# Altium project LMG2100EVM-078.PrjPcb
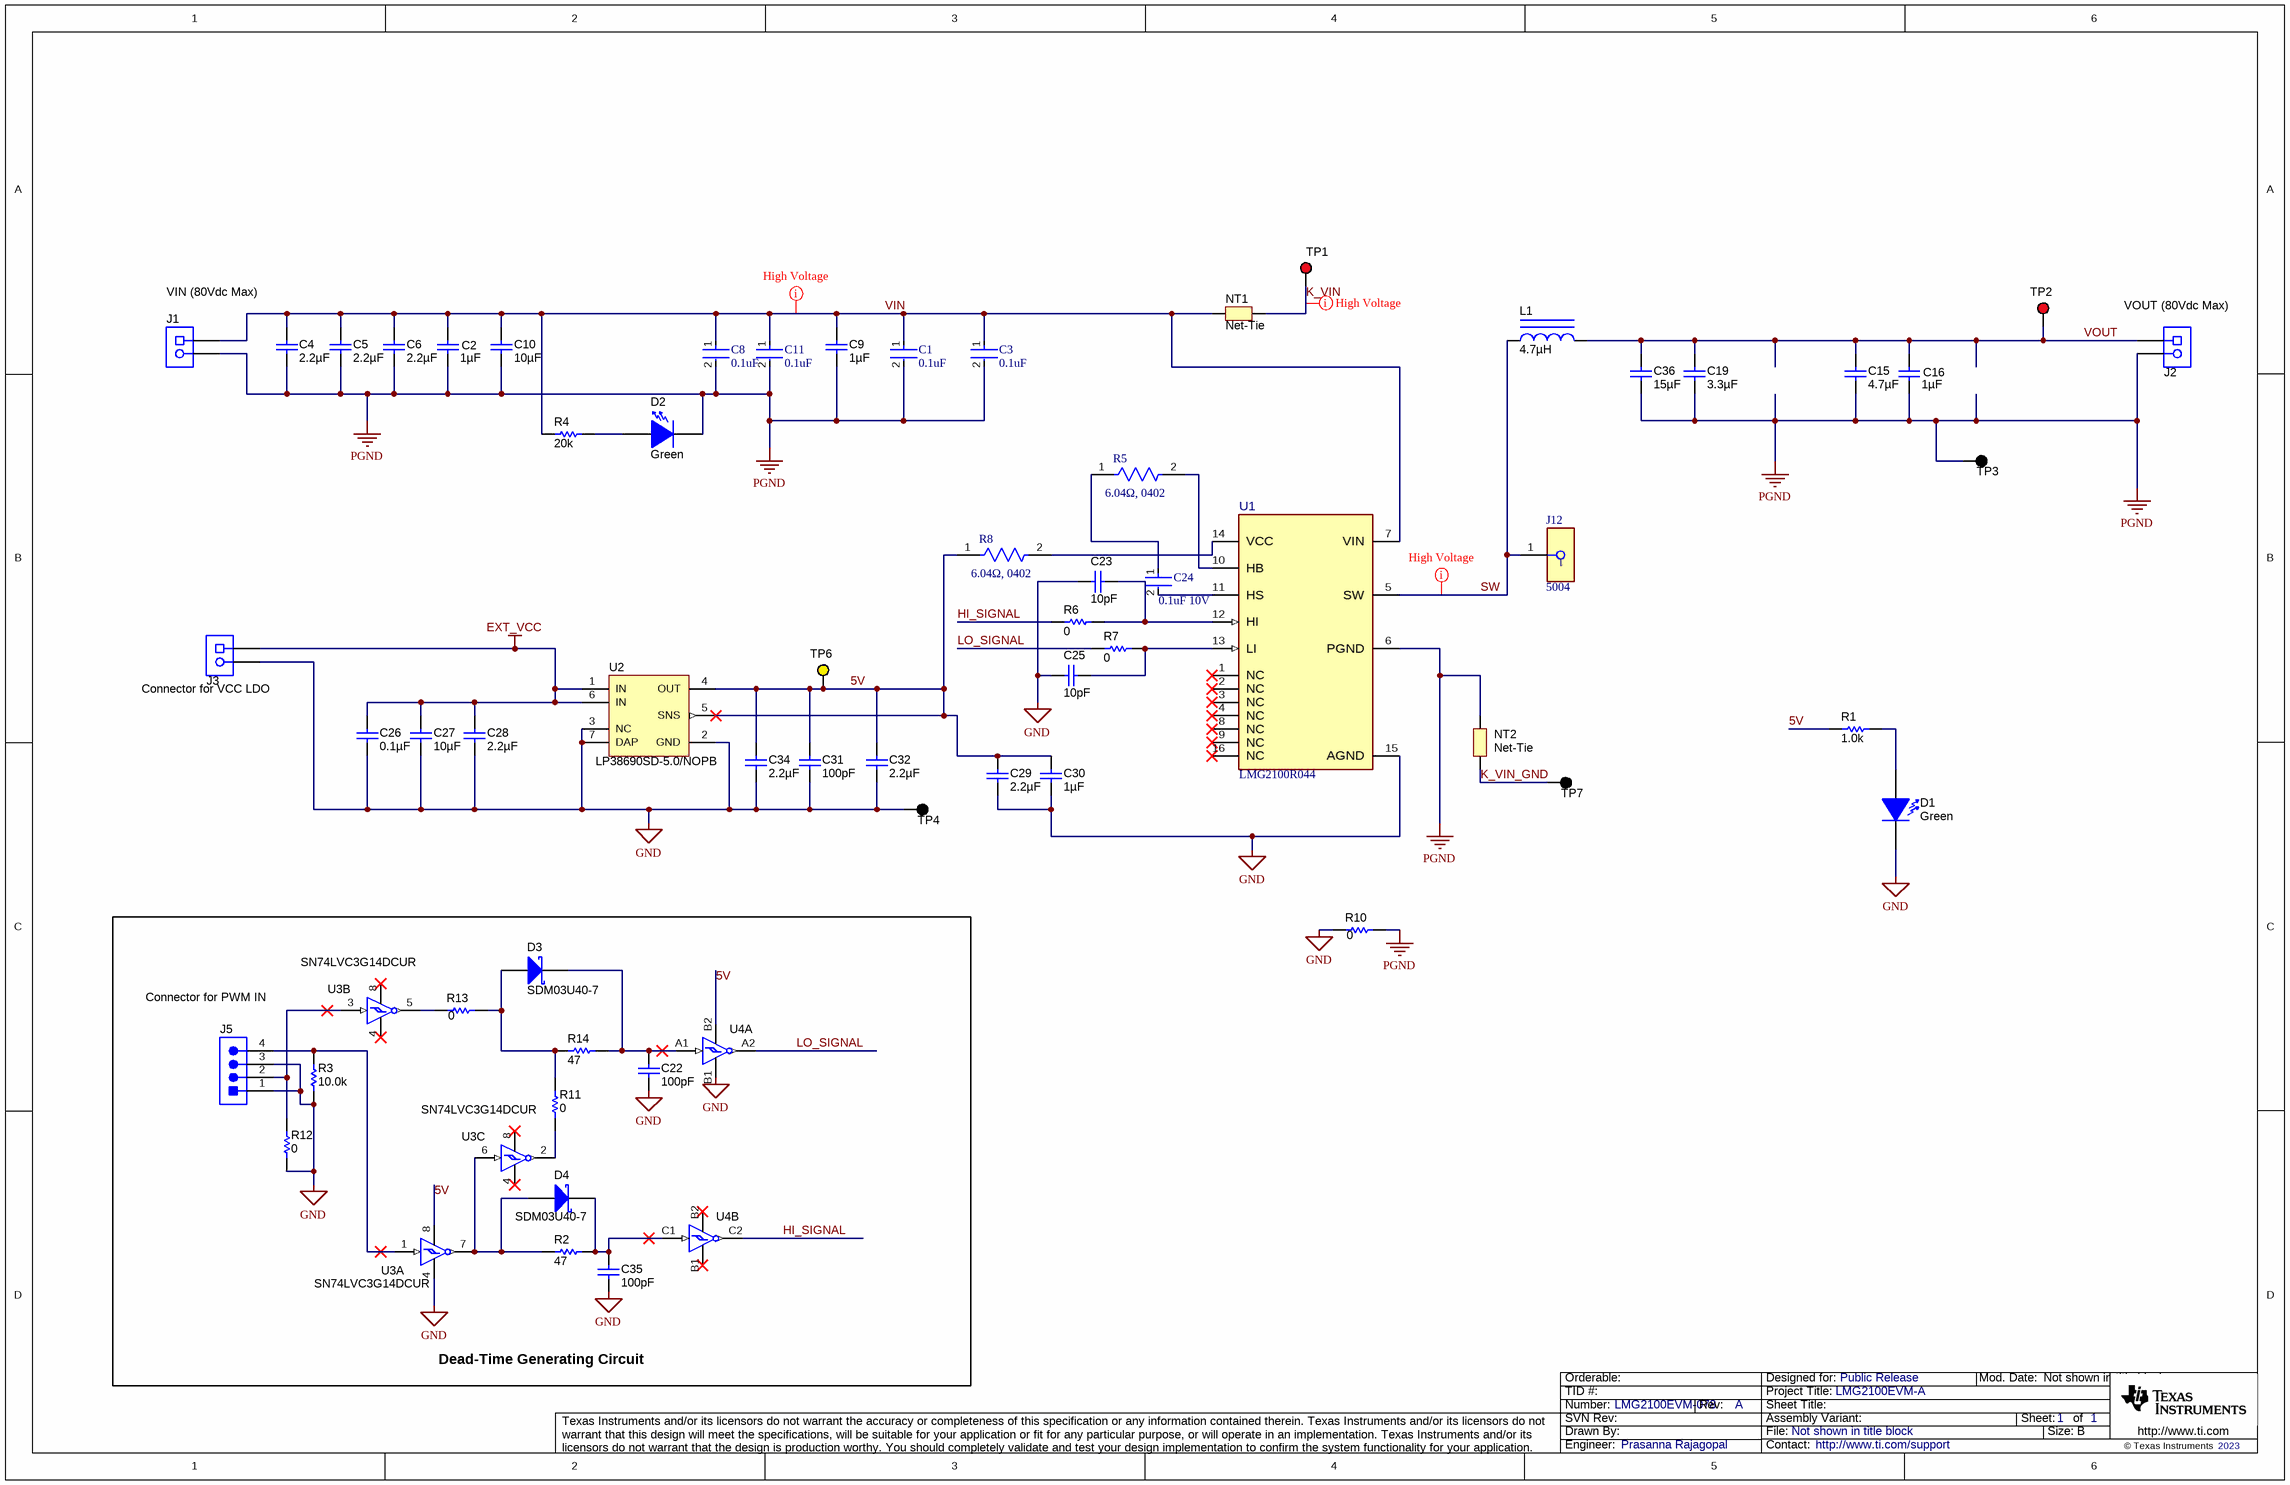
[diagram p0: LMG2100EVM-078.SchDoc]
CopyrightYear: 2023; PCB_Layout: Prasanna Rajagopal; PCB_Rev: A; PRJ_Customer: Public Release; PRJ_Engineer: Prasanna Rajagopal; PRJ_Number: LMG2100EVM-078; PRJ_Title: LMG2100EVM-A; SCH_Rev: A; TechSupport: http://www.ti.com/support
2 sheets, 79 parts. Net scope: global (net labels, ports and power ports of the same name join across sheets).
Board file: LMG2100EVM-078.PcbDoc
Sheets:
  LMG2100EVM-078.SchDoc
  LMG2100EVM-078_hardware.SchDoc

## Sheet LMG2100EVM-078.SchDoc
size 431 x 279 mm; Date: Not shown in title block; ApprovedBy: Not shown in title block; CheckedBy: Not shown in title block; Author: Not shown in title block; CompanyName: Not shown in title block; Engineer: Not shown in title block; Organization: Not shown in title block; Address1: Not shown in title block; Address2: Not shown in title block; Address3: Not shown in title block; Address4: Not shown in title block; DocumentNumber: 1; Revision: Use project parameter SCH_Rev; SheetNumber: 1; SheetTotal: 1; PageSetup: Record=PageOptions¦CenterHorizontal=True¦CenterVertical=True¦PrintScale=1.00¦XCorrection=1.00¦YCorrection=1.00¦PrintKind=0¦BorderSize=5000000¦LeftOffset=0¦BottomOffset=0¦Orientation=2¦PaperLength=1000¦PaperWidth=1000¦Scale=100¦PaperSource=15¦PrintQuality=600¦MediaType=1¦DitherType=10¦PaperKind=Letter¦PrintScaleMode=1

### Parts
C1  0.1uF  [FP-GRM155-0_05-IPC_A]
C2  ValueDisplayed: 1µF  [1206]  (hidden comment: C3216X7R2A105M160AA)
C3  0.1uF  [FP-GRM155-0_05-IPC_A]
C4  ValueDisplayed: 2.2µF  [1210_270]  (hidden comment: GRM32ER72A225KA35L)
C5  ValueDisplayed: 2.2µF  [1210_270]  (hidden comment: GRM32ER72A225KA35L)
C6  ValueDisplayed: 2.2µF  [1210_270]  (hidden comment: GRM32ER72A225KA35L)
C8  0.1uF  [FP-GRM155-0_05-IPC_A]
C9  ValueDisplayed: 1µF  [1206]  (hidden comment: C3216X7R2A105M160AA)
C10  ValueDisplayed: 10µF  [2220_280]  (hidden comment: 22201C106MAT2A)
C11  0.1uF  [FP-GRM155-0_05-IPC_A]
C15  ValueDisplayed: 4.7µF  [1210]  (hidden comment: C3225X7S2A475K200AE)
C16  ValueDisplayed: 1µF  [0805_HV]  (hidden comment: C2012X7S2A105K125AB)
C19  ValueDisplayed: 3.3µF  [1206_190]  (hidden comment: C3216X7S2A335M160AB)
C22  ValueDisplayed: 100pF  [0402]  (hidden comment: CC0402JRNPO9BN101)
C23  ValueDisplayed: 10pF  [0402]  (hidden comment: GRM1555C1H100JA01D)
C24  0.1uF 10V  [FP-C1005-050-0_05-IPC_A]
C25  ValueDisplayed: 10pF  [0402]  (hidden comment: GRM1555C1H100JA01D)
C26  ValueDisplayed: 0.1µF  [0603]  (hidden comment: 0603YC104JAT2A)
C27  ValueDisplayed: 10µF  [0805_HV]  (hidden comment: C2012X5R1E106K125AB)
C28  ValueDisplayed: 2.2µF  [0805_HV]  (hidden comment: C0805C225K4RACTU)
C29  ValueDisplayed: 2.2µF  [0805_HV]  (hidden comment: C0805C225K4RACTU)
C30  ValueDisplayed: 1µF  [0402]  (hidden comment: C1005X5R1E105K050BC)
C31  ValueDisplayed: 100pF  [0603]  (hidden comment: 06033C101KAT2A)
C32  ValueDisplayed: 2.2µF  [0603_HV]  (hidden comment: GRM188R71A225KE15D)
C34  ValueDisplayed: 2.2µF  [0603_HV]  (hidden comment: GRM188R71A225KE15D)
C35  ValueDisplayed: 100pF  [0402]  (hidden comment: CC0402JRNPO9BN101)
C36  ValueDisplayed: 15µF  [2220_280]  (hidden comment: C5750X7S2A156M250KB)
D1  value Green  [LTST-C170KGKT_Green]  (hidden comment: VCC_5V)
D2  value Green  [LTST-C170KGKT_Green]  (hidden comment: VIN)
D3  SDM03U40-7  [SOD-523]
D4  SDM03U40-7  [SOD-523]
J1  VIN (80Vdc Max)  [TEC_282841-2]
J2  VOUT (80Vdc Max)  [TEC_282841-2]
J3  282834-2  [TEC_282834-2]  (value not drawn)
J5  5-146278-4  [TE_5-146278-4]  (value not drawn)
J12  5004  [FP-5004-MFG]
L1  ValueDisplayed: 4.7µH  [XAL8080]  (hidden comment: XAL1010-472ME)
NT1  Net-Tie  [Net-Tie_10milWide_30milLong]  (net tie, no BOM)
NT2  Net-Tie  [Net-Tie_10mil]  (net tie, no BOM)
R1  value 1.0k  [0603]  (hidden comment: CRCW06031K00JNEA)
R2  value 47  [0402]  (hidden comment: CRCW040247R0JNED)
R3  value 10.0k  [0402]  (hidden comment: CRCW040210K0FKED)
R4  value 20k  [1206]  (hidden comment: CRCW120620K0JNEA)
R5  6.04Ω, 0402  [FP-CRCW0402-e3-IPC_A]
R6  value 0  [0603]  (hidden comment: CRCW06030000Z0EA)
R7  value 0  [0603]  (hidden comment: CRCW06030000Z0EA)
R8  6.04Ω, 0402  [FP-CRCW0402-e3-IPC_A]
R10  value 0  [0603]  (hidden comment: CRCW06030000Z0EA)
R11  value 0  [0402]  (hidden comment: CRCW04020000Z0ED)
R12  value 0  [0402]  (hidden comment: CRCW04020000Z0ED)
R13  value 0  [0402]  (hidden comment: CRCW04020000Z0ED)
R14  value 47  [0402]  (hidden comment: CRCW040247R0JNED)
TP1  5000  [Keystone5000]  (value not drawn)
TP2  VOUT Sense+  [Keystone5000]  (value not drawn)
TP3  VOUT Sense-  [Keystone5001]  (value not drawn)
TP4  5001  [Keystone5001]  (value not drawn)
TP6  5004  [Keystone5004]  (value not drawn)
TP7  5001  [Keystone5001]  (value not drawn)
U1  LMG2100R044  [RAR0016A-MFG]
U2  LP38690SD-5.0/NOPB  [SDE06A_full]
U3  SN74LVC3G14DCUR  [DCU0008A_N]  (parts A,B,C of 3)
U4  SN74LVC2G14YZPR  [YZP0006ADBD]  (value not drawn)  (parts A,B of 2)

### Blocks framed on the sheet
Dead-Time Generating Circuit: C22 C35 D3 D4 J5 R2 R3 R11-R14 U3 U4

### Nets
EXT_VCC: C26.1 C27.2 C28.2 J3.1 U2.1(IN) U2.6(IN)
GND: C22.2 C23.1 C25.2 C26.2 C27.1 C28.1 C29.1 C30.2 C31.1 C32.2 C34.2 C35.2 D1.2(K) J3.2 J5.1 J5.3 R3.2 R10.2 R12.1 TP4.1 U1.15(AGND) U2.2(GND) U2.3(NC) U2.7(DAP) U3.4(GND) U4.B1(GND)
PGND: C1.2 C2.1 C3.2 C4.2 C5.2 C6.2 C8.2 C9.1 C10.1 C11.2 C15.2 C16.2 C19.2 C36.2 D2.2(K) J1.2 J2.2 NT2.2 R10.1 TP3.1 U1.6(PGND)
5V: C29.2 C30.1 C31.2 C32.1 C34.1 R1.1 R8.1 TP6.1 U2.4(OUT) U2.5(SNS) U3.8(VCC) U4.B2(VCC)
HI_SIGNAL: R6.2 U4.C2(2Y)
K_VIN: NT1.2 TP1.1
K_VIN_GND: NT2.1 TP7.1
LO_SIGNAL: R7.2 U4.A2(1Y)
SW: J12.1 L1.1 U1.5(SW)
VIN: C1.1 C2.2 C3.1 C4.1 C5.1 C6.1 C8.1 C9.2 C10.2 C11.1 J1.1 NT1.1 R4.1 U1.7(VIN)
VOUT: C15.1 C16.1 C19.1 C36.1 J2.1 L1.2 TP2.1
NetC22_1: C22.1 D3.1(K) R14.2 U4.A1(1A)
NetC23_2: C23.2 R6.1 U1.12(HI)
NetC24_1: C24.1 R5.1
NetC24_2: C24.2 U1.11(HS)
NetC25_1: C25.1 R7.1 U1.13(LI)
NetC35_1: C35.1 D4.1(K) R2.2 U4.C1(2A)
NetD1_1: D1.1(A) R1.2
NetD2_1: D2.1(A) R4.2
NetD3_2: D3.2(A) R11.1 R13.2 R14.1
NetD4_2: D4.2(A) R2.1 U3.6(3A) U3.7(1Y)
NetJ5_2: J5.2 R12.2 U3.3(2A)
NetJ5_4: J5.4 R3.1 U3.1(1A)
NetR5_2: R5.2 U1.10(HB)
NetR8_2: R8.2 U1.14(VCC)
NetR11_2: R11.2 U3.2(3Y)
NetR13_1: R13.1 U3.5(2Y)

Not connected (* = marked no-connect by the designer): U1 1(NC)* 2(NC)* 3(NC)* 4(NC)* 8(NC)* 9(NC)* 16(NC)*

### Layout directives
rule Routing Corners [Style - 45 Degree    Min Setback = 100mil    Max Setback = 100mil]; rule Clearance Constraint [Clearance = 25mil]: SW, VIN
rule Routing Corners [Style - 45 Degree    Min Setback = 100mil    Max Setback = 100mil]; rule Clearance Constraint [Clearance = 23.6mil]: K_VIN

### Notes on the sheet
- (near J3) Connector for VCC LDO
- (near J5) Connector for PWM IN

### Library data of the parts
C1 C3 C8 C11 = CMP-06035-008289-1: Chip Multilayer Ceramic Capacitors for General Purpose, 0402, 0.10uF, X5R, 15%, 10%, 100V; Capacitance: 100nF
C2 C9 = C3216X7R2A105M160AA: CAP, CERM, 1uF, 100V, +/-20%, X7R, 1206; Manufacturer: TDK; CompType: Capacitor; VDC_V: 100; Tolerance_%: 20; Polarized: N; TaMax_C: 125; TaMin_C: -55; Cap_F: 0.000001; U/M: EA; Value1: Unknown
C4-C6 = GRM32ER72A225KA35L: CAP, CERM, 2.2 µF, 100 V, +/- 10%, X7R, 1210; Manufacturer: MuRata; Polarized: N; CompType: Capacitor; Value: 2.2uF; U/M: EA; Cap_F: 0.0000022; Tolerance_%: 10; ESR_ohm: 0.007; Value1: 0.007 ohm; VDC_V: 100; Value2: 100V; IRMS_A: 4.4; TaMin_C: -55; TaMax_C: 125; Cap_Case: 1210; SizeArea_mm2: 8; SizeAreaWB_mm2: 14.7; SizeX_mm: 3.2; SizeY_mm: 2.5; SizeZ_mm: 2.7; AEC Category: Q200
C10 = 22201C106MAT2A: CAP, CERM, 10 µF, 100 V, +/- 20%, X7R, 2220; Manufacturer: AVX; CompType: Capacitor; Value: 10uF; VDC_V: 100; Tolerance_%: 20; Cap_Case: 2220; Polarized: N; TaMax_C: 125; TaMin_C: -55; Cap_F: 0.00001; U/M: EA; Value1: Unknown; Value2: 100V; SizeArea_mm2: 28.5; SizeAreaWB_mm2: 53.9; SizeX_mm: 5.7; SizeY_mm: 5; SizeZ_mm: 2.8; AEC Category: Q200
C15 = C3225X7S2A475K200AE: CAP, CERM, 4.7 µF, 100 V, +/- 10%, X7S, 1210; Manufacturer: TDK; CompType: Capacitor; VDC_V: 100; Tolerance_%: 10; Value: 4.7uF; Polarized: N; TaMax_C: 125; TaMin_C: -55; Cap_F: 0.0000047; U/M: EA; Value1: Unknown; Value2: 100V; SizeArea_mm2: 8; SizeAreaWB_mm2: 14.7; SizeX_mm: 3.2; SizeY_mm: 2.5; SizeZ_mm: 1.35; AEC Category: Q200
C16 = C2012X7S2A105K125AB: CAP, CERM, 1 µF, 100 V, +/- 10%, X7S, 0805; Manufacturer: TDK; Cap_Case: 0805; ESR_ohm: 0.008255; IRMS_A: 2.27442; Polarized: N; TaMax_C: 125; TaMin_C: -55; Tolerance_%: 10; VDC_V: 100; Cap_F: 0.000001; CompType: Capacitor; Value: 1uF; U/M: EA; Value1: 0.008255 ohm; Value2: 100V; SizeArea_mm2: 2.5; SizeAreaWB_mm2: 6.75; SizeX_mm: 2; SizeY_mm: 1.25; SizeZ_mm: 1.45; AEC Category: Q200
C19 = C3216X7S2A335M160AB: CAP, CERM, 3.3 µF, 100 V, +/- 20%, X7S, 1206_190; Manufacturer: TDK; Polarized: N; CompType: Capacitor; Value: 3.3uF; U/M: EA; Cap_F: 0.0000033; Tolerance_%: 20; ESR_ohm: 0.003048; Value1: 0.003048 ohm; VDC_V: 100; Value2: 100V; IRMS_A: 4.15703; TaMin_C: -55; TaMax_C: 125; SizeArea_mm2: 5.12; SizeAreaWB_mm2: 10.92; SizeX_mm: 3.2; SizeY_mm: 1.6; SizeZ_mm: 1.9; AEC Category: Q200
C22 C35 = CC0402JRNPO9BN101: CAP, CERM, 100pF, 50V, +/-5%, C0G/NP0, 0402; Manufacturer: Yageo America; Polarized: N; CompType: Capacitor; U/M: EA; Cap_F: 0.0000000001; Tolerance_%: 5; Value1: Unknown; VDC_V: 50; TaMin_C: -55; TaMax_C: 125
C23 C25 = GRM1555C1H100JA01D: CAP, CERM, 10pF, 50V, +/-5%, C0G/NP0, 0402; Manufacturer: MuRata; Polarized: N; CompType: Capacitor; U/M: EA; Cap_F: 0.00000000001; Tolerance_%: 5; Value1: Unknown; VDC_V: 50; TaMin_C: -55; TaMax_C: 125
C24 = CMP-08246-002729-1: Multilayer Ceramic Capacitors 100nF ±10% 10V X5R SMD 0402
C26 = 0603YC104JAT2A: CAP, CERM, 0.1 µF, 16 V, +/- 5%, X7R, 0603; Manufacturer: AVX; ESR_ohm: 0.039; Polarized: N; TaMax_C: 125; TaMin_C: -55; Tolerance_%: 5; VDC_V: 16; Cap_F: 0.0000001; CompType: Capacitor; Value: 0.1uF; U/M: EA; Value1: 0.039 ohm; Value2: 16V
C27 = C2012X5R1E106K125AB: CAP, CERM, 10uF, 25V, +/-10%, X5R, 0805; Manufacturer: TDK; CompType: Capacitor; VDC_V: 25; Tolerance_%: 10; Cap_Case: 0805; Polarized: N; TaMax_C: 85; TaMin_C: -55; Cap_F: 0.00001; U/M: EA; Value1: Unknown
C28 C29 = C0805C225K4RACTU: CAP, CERM, 2.2uF, 16V, +/-10%, X7R, 0805; Manufacturer: Kemet; CompType: Capacitor; VDC_V: 16; Tolerance_%: 10; Cap_Case: 0805; ESR_Ohm: 0.008; IRMS_A: 15.55; Polarized: N; TaMax_C: 125; TaMin_C: -55; Cap_F: 0.0000022; U/M: EA; Value1: 0.008 ohm
C30 = C1005X5R1E105K050BC: CAP, CERM, 1uF, 25V, +/-10%, X5R, 0402; Manufacturer: TDK; Polarized: N; TaMax_C: 80; TaMin_C: -55; Tolerance_%: 10; VDC_V: 25; Cap_F: 0.000001; CompType: Capacitor; U/M: EA; Value1: Unknown
C31 = 06033C101KAT2A: CAP, CERM, 100pF, 25V, +/-10%, X7R, 0603; Manufacturer: AVX; Polarized: N; TaMax_C: 125; TaMin_C: -55; Tolerance_%: 10; VDC_V: 25; Cap_F: 0.0000000001; CompType: Capacitor; U/M: EA
C32 C34 = GRM188R71A225KE15D: CAP, CERM, 2.2uF, 10V, +/-10%, X7R, 0603; Manufacturer: MuRata; Cap_Case: 0603; ESR_Ohm: 0.009; Polarized: N; TaMax_C: 125; TaMin_C: -55; Tolerance_%: 10; Cap_F: 0.0000022; CompType: Capacitor; U/M: EA; Value1: 0.009 ohm
C36 = C5750X7S2A156M250KB: CAP, CERM, 15 µF, 100 V, +/- 20%, X7S, 2220; Manufacturer: TDK; CompType: Capacitor; VDC_V: 100; Tolerance_%: 20; Value: 15uF; ESR_ohm: 0.002642; IRMS_A: 5.61617; Polarized: N; TaMax_C: 125; TaMin_C: -55; Cap_F: 0.000015; U/M: EA; Value1: 0.002642 ohm; Value2: 100V; SizeArea_mm2: 28.5; SizeAreaWB_mm2: 53.9; SizeX_mm: 5.7; SizeY_mm: 5; SizeZ_mm: 2.8; AEC Category: Q200
D1 D2 = LTST-C170KGKT: LED, Green, SMD; Manufacturer: Lite-On; Type: AlInGaP; Vf_V: 2; Value2: 2V; Io_A: 0.02; Value1: W; U/M: EA
D3 D4 = SDM03U40-7: Diode, Schottky, 40V, 0.03A, SOD-523; Manufacturer: Diodes Inc.; U/M: EA; Vf_V: 1; Value2: 1V; Io_A: 0.03; Vr_V: 40; TJmax_C: 125
J1 J2 = 282841-2: Terminal Block, 2x1, 5.08mm, TH; Manufacturer: TE Connectivity; SymbolCreator: a0412235; U/M: EA
J3 = 282834-2: Terminal Block, 2x1, 2.54mm, TH; Manufacturer: TE Connectivity; SymbolCreator: a0412235; U/M: EA
J5 = 5-146278-4: Header, 100mil, 4x1, Tin, TH; Manufacturer: TE Connectivity; SymbolCreator: a0412235; U/M: EA
J12 = CMP-2000-05575-2: PC TEST POINT MINIATURE YELLOW; Manufacturer: Keystone; Number Of Contacts: 1; Is Female: yes
L1 = XAL8080-472ME: Inductor, Shielded, Composite, 4.7 µH, 10.5 A, 0.00889 ohm, SMD; Manufacturer: Coilcraft; Value: 4.7uH; Ind_H: 4.7E-6; Imax_A: 10.5; Irms: 10.5A @ 20C rise; Isat: 17.4A @ 20% inductance drop; Value2: 10.5A; SizeAreaWB_mm2: 107.06; SizeArea_mm2: 69.66; SizeX_mm: 8.1; SizeY_mm: 8.6; SizeZ_mm: 8; AEC Category: Q200
NT1 NT2 = Net-Tie: Single point connection between nets.; SymbolCreator: codlsc
R1 = CRCW06031K00JNEA: RES, 1.0k ohm, 5%, 0.1W, 0603; Manufacturer: Vishay-Dale; CompType: Resistor; Res_ohm: 1000; Value_Code: 1k00; Tolerance_%: 5; Power_W: 0.1; VDC_V: 75; TempCo: 200 ppm/C; EIA_Code: E24; U/M: EA
R2 R14 = CRCW040247R0JNED: RES, 47 ohm, 5%, 0.063W, 0402; Manufacturer: Vishay-Dale; CompType: Resistor; Value_Code: 47R0; Tolerance_%: 5; Power_W: 0.063; VDC_V: 50; TempCo: 200 ppm/C; EIA_Code: E24; U/M: EA
R3 = CRCW040210K0FKED: RES, 10.0k ohm, 1%, 0.063W, 0402; Manufacturer: Vishay-Dale; CompType: Resistor; Res_ohm: 10000; Value_Code: 10k0; Tolerance_%: 1; Power_W: 0.063; VDC_V: 50; TempCo: 100 ppm/C; EIA_Code: E96; U/M: EA
R4 = CRCW120620K0JNEA: RES, 20k ohm, 5%, 0.25W, 1206; Manufacturer: Vishay-Dale; CompType: Resistor; Res_ohm: 20000; Value_Code: 20k0; Tolerance_%: 5; Power_W: 0.25; VDC_V: 200; TempCo: 200 ppm/C; EIA_Code: E24; U/M: EA
R5 R8 = CMP-1011-00259-3: RES Thick Film, 6.04Ω, 1%, 0.063W, 100ppm/°C, 0402; Voltage Rating: 50V; Resistance: 6.04R; Power Rating: 63mW
R6 R7 R10 = CRCW06030000Z0EA: RES, 0 ohm, 5%, 0.1W, 0603; Manufacturer: Vishay-Dale; CompType: Resistor; Value_Code: 0000; Tolerance_%: 5; Power_W: 0.1; VDC_V: 75; TempCo: 200 ppm/C; EIA_Code: E24; U/M: EA
R11-R13 = CRCW04020000Z0ED: RES, 0 ohm, 5%, 0.063W, 0402; Manufacturer: Vishay-Dale; CompType: Resistor; Value_Code: 0000; Tolerance_%: 5; Power_W: 0.063; VDC_V: 50; TempCo: 200 ppm/C; EIA_Code: E24; U/M: EA
TP1 TP2 = 5000: Test Point, Miniature, Red, TH; Manufacturer: Keystone; CompType: Test Point Loop; U/M: EA
TP3 TP4 TP7 = 5001: Test Point, Miniature, Black, TH; Manufacturer: Keystone; CompType: Test Point Loop; U/M: EA
TP6 = 5004: Test Point, Miniature, Yellow, TH; Manufacturer: Keystone; CompType: Test Point Loop; ContactFinish: Silver
U1 = CMP-0097820-2: Manufacturer: Texas Instruments; AEC Category: Q200; CompType: IC; Standoff Height: 0mm; SizeZ_mm: 0.89mm
U2 = LP38690SD-5.0/NOPB: 1A Low Dropout CMOS Linear Regulators Stable with Ceramic Output Capacitors, 6-pin LLP, Pb-Free; Manufacturer: Texas Instruments; PackageTopMarking: ZXYTT*L116B; PowerWise: Y; CompType: LDO IC
U3 = SN74LVC3G14DCUR: Triple Schmitt-Trigger Inverter, DCU0008A; Manufacturer: Texas Instruments; Alternate PartNumber: SN74LVC3G14DCUT; SymbolCreator: Altium; CompType: IC; U/M: EA
U4 = SN74LVC2G14YZPR: Dual Schmitt-Trigger Inverter, YZP0006ADBD (DSBGA-6); Manufacturer: Texas Instruments; SymbolCreator: Altium; SizeArea_mm2: 1.232544; SizeAreaWB_mm2: 4.508544; SizeX_mm: 0.888; SizeY_mm: 1.388; SizeZ_mm: 0.5; CompType: IC; U/M: EA

## Sheet LMG2100EVM-078_hardware.SchDoc
size 431 x 279 mm; Date: Not shown in title block; ApprovedBy: Not shown in title block; CheckedBy: Not shown in title block; Author: Not shown in title block; CompanyName: Not shown in title block; Engineer: Not shown in title block; Organization: Not shown in title block; Address1: Not shown in title block; Address2: Not shown in title block; Address3: Not shown in title block; Address4: Not shown in title block; DocumentNumber: 1; Revision: Use project parameter SCH_Rev; SheetNumber: 2; SheetTotal: 1; PageSetup: Record=PageOptions¦CenterHorizontal=True¦CenterVertical=True¦PrintScale=1.00¦XCorrection=1.00¦YCorrection=1.00¦PrintKind=0¦BorderSize=5000000¦LeftOffset=0¦BottomOffset=0¦Orientation=2¦PaperLength=1000¦PaperWidth=1000¦Scale=100¦PaperSource=15¦PrintQuality=600¦MediaType=1¦DitherType=10¦PaperKind=Letter¦PrintScaleMode=1
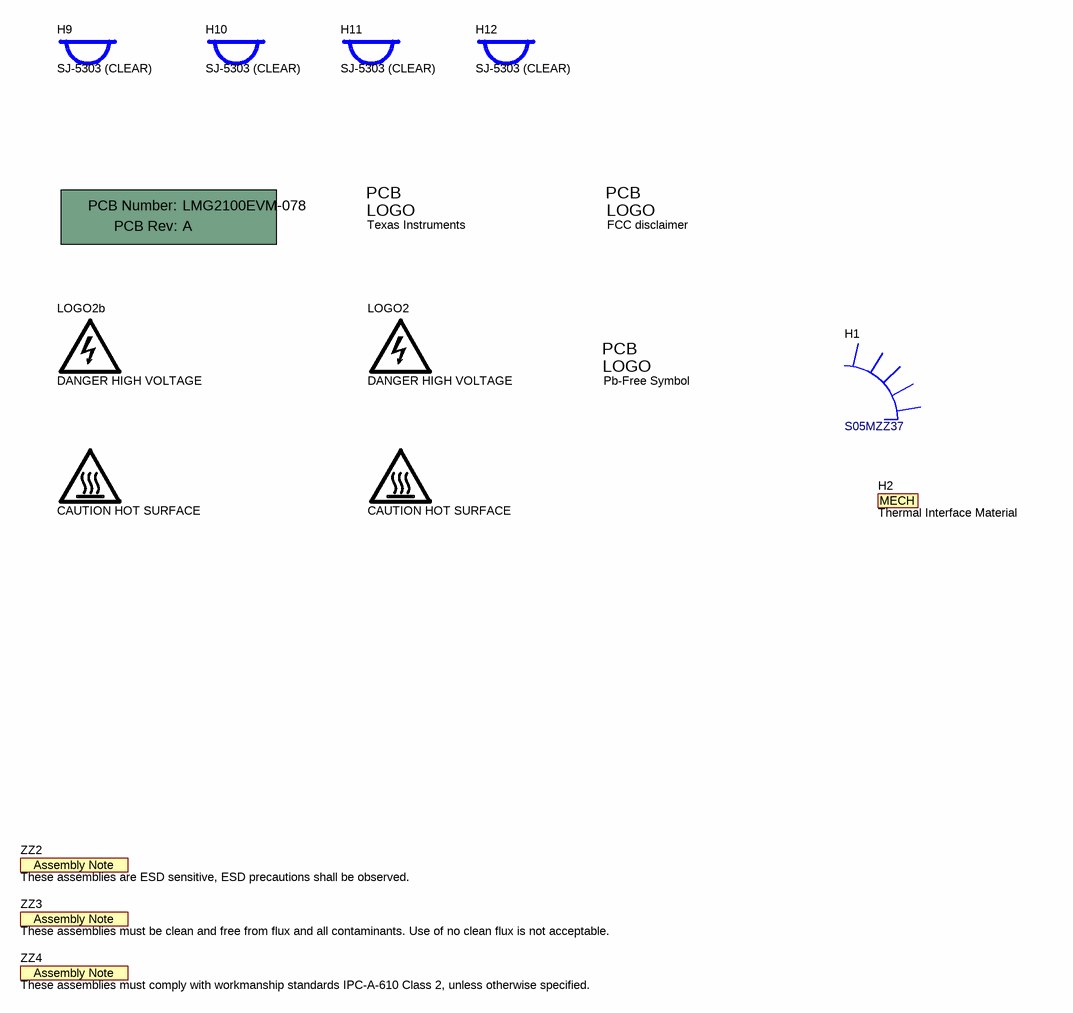
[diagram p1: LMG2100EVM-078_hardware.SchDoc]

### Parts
!PCB1  Printed Circuit Board  (value not drawn)  (mechanical)
H1  S05MZZ37  [S05MZZ14]
H2  Thermal Interface Material  (mechanical)
H9  SJ-5303 (CLEAR)  [Bumpon_SJ5003Transparent]  (no BOM)
H10  SJ-5303 (CLEAR)  [Bumpon_SJ5003Transparent]  (no BOM)
H11  SJ-5303 (CLEAR)  [Bumpon_SJ5003Transparent]  (no BOM)
H12  SJ-5303 (CLEAR)  [Bumpon_SJ5003Transparent]  (no BOM)
Logo1  Texas Instruments  [TI_Stacked_Overlay_Small]  (no BOM)
LOGO2  DANGER HIGH VOLTAGE  [IEC_HighVoltage_Small]  (no BOM)
LOGO2b  DANGER HIGH VOLTAGE  [IEC_HighVoltage_Small]  (no BOM)
LOGO3  CAUTION HOT SURFACE  [IEC_HotSurface_Small]  (no BOM)
LOGO3b  CAUTION HOT SURFACE  [IEC_HotSurface_Small]  (no BOM)
Logo4  FCC disclaimer  [FCC_disclaimer_stacked]  (no BOM)
Logo5  Pb-Free Symbol  [Pb-Free_Overlay_Small]  (no BOM)
ZZ2  These assemblies are ESD sensitive, ESD precautions shall be observed.  [AssemblyNote]  (no BOM)
ZZ3  These assemblies must be clean and free from flux and all contaminants. Use of no clean flux is not acceptable.  [AssemblyNote]  (no BOM)
ZZ4  These assemblies must comply with workmanship standards IPC-A-610 Class 2, unless otherwise specified.  [AssemblyNote]  (no BOM)

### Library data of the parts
!PCB1 = PCB: Manufacturer: Any; PartNumber: LMG2100EVM-078; SymbolCreator: a0412235
H1 = HeatSink_NoPins: Heat Sink, Black Anodized, 35 x 50 mm,  20 mm high, with Push Pin and Spring; Manufacturer: Alpha Novatech
H2 = CMP-0080604-2: Manufacturer: Fuji Polymer Industries; PartNumber: GR80A-0H-50GY; CompType: Mechanical
H9-H12 = SJ-5303 (CLEAR): Bumpon, Hemisphere, 0.44 X 0.20, Clear; Manufacturer: 3M; SymbolCreator: a0412235
Logo1 = TI_Logo: Texas Instrument Corporate Signature; SymbolCreator: a0412235
LOGO2 LOGO2b = IEC_HighVoltage: IEC 61010-1 High Voltage Warning; SymbolCreator: a0412235
LOGO3 LOGO3b = IEC_HotSurface: IEC 61010-1 Hot Surface Warning; SymbolCreator: a0412235
Logo4 = FCC_disclaimer: SymbolCreator: codlsc
Logo5 = Pb-Free: SymbolCreator: a0412235
ZZ2-ZZ4 = AssemblyNote: SymbolCreator: codlsc

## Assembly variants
001: not fitted C7 C12 R13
